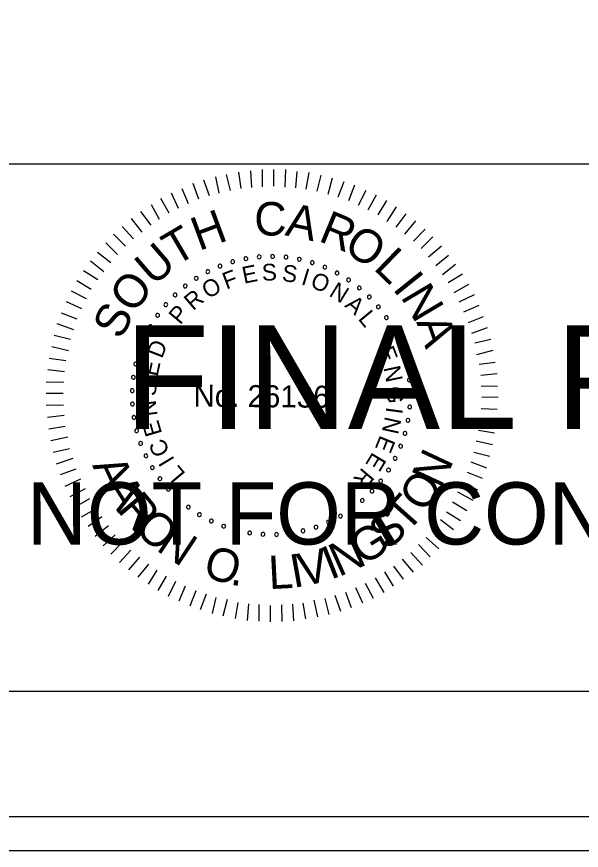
# Model space of a CAD drawing. Extents: x 967 to 1326, y 964 to 2584.
# Drawn here: x 1170.56 to 1189.3, y 1803.72 to 1831.36 of the extents above; entities that cross this region are included whole.
import ezdxf

# ---------------------------------------------------------------- set-up
doc = ezdxf.new("R2010")
doc.units = 0
for name, color, linetype in [('RD_SHT_Misc1', 7, 'Continuous'), ('RD_SHT_Misc2', 7, 'Continuous'), ('RD_XS_ExPaveRet', 7, 'Continuous'), ('RD_XS_TX_Elev_EX', 7, 'Continuous')]:
    doc.layers.add(name, color=color, linetype=linetype)

msp = doc.modelspace()

# ---------------------------------------------------------------- linework, layer by layer
at = {"layer": 'RD_SHT_Misc1'}
for p, q in [((1178.01, 1825.663), (1177.93, 1826.209)), ((1178.364, 1825.699), (1178.33, 1826.244)), ((1178.717, 1825.719), (1178.722, 1826.295)), ((1179.093, 1825.739), (1179.098, 1826.292)), ((1179.469, 1825.713), (1179.489, 1826.288)), ((1179.829, 1825.687), (1179.872, 1826.231)), ((1180.174, 1825.646), (1180.271, 1826.19)), ((1176.964, 1825.419), (1176.769, 1825.935)), ((1177.287, 1825.508), (1177.169, 1826.054)), ((1177.657, 1825.597), (1177.53, 1826.128)), ((1180.535, 1825.573), (1180.662, 1826.102)), ((1180.902, 1825.478), (1181.045, 1826.022)), ((1181.231, 1825.384), (1181.428, 1825.896)), ((1176.264, 1825.156), (1176.053, 1825.657)), ((1176.61, 1825.306), (1176.423, 1825.83)), ((1181.584, 1825.265), (1181.78, 1825.786)), ((1181.905, 1825.109), (1182.154, 1825.606)), ((1175.624, 1824.846), (1175.352, 1825.332)), ((1175.933, 1825.005), (1175.699, 1825.506)), ((1182.226, 1824.953), (1182.506, 1825.45)), ((1175.308, 1824.634), (1175.036, 1825.12)), ((1182.562, 1824.789), (1182.85, 1825.27)), ((1175.03, 1824.445), (1174.681, 1824.9)), ((1182.86, 1824.572), (1183.163, 1825.053)), ((1183.158, 1824.378), (1183.484, 1824.828)), ((1174.729, 1824.217), (1174.372, 1824.665)), ((1183.447, 1824.145), (1183.811, 1824.587)), ((1174.435, 1823.997), (1174.062, 1824.399)), ((1183.729, 1823.92), (1184.116, 1824.316)), ((1174.172, 1823.753), (1173.776, 1824.148)), ((1183.98, 1823.672), (1184.368, 1824.061)), ((1173.909, 1823.479), (1173.52, 1823.858)), ((1184.232, 1823.394), (1184.657, 1823.767)), ((1173.684, 1823.197), (1173.242, 1823.546)), ((1184.475, 1823.108), (1184.892, 1823.45)), ((1173.451, 1822.9), (1173.009, 1823.256)), ((1184.687, 1822.807), (1185.128, 1823.156)), ((1173.257, 1822.64), (1172.776, 1822.936)), ((1173.039, 1822.312), (1172.559, 1822.6)), ((1184.885, 1822.544), (1185.355, 1822.832)), ((1185.081, 1822.213), (1185.56, 1822.493)), ((1172.883, 1822.006), (1172.379, 1822.256)), ((1185.24, 1821.904), (1185.756, 1822.145)), ((1172.727, 1821.677), (1172.215, 1821.904)), ((1185.399, 1821.573), (1185.907, 1821.791)), ((1172.571, 1821.333), (1172.051, 1821.53)), ((1185.549, 1821.226), (1186.057, 1821.414)), ((1172.461, 1820.974), (1171.91, 1821.178)), ((1185.669, 1820.865), (1186.185, 1821.06)), ((1172.351, 1820.652), (1171.807, 1820.787)), ((1185.759, 1820.541), (1186.297, 1820.667)), ((1172.286, 1820.276), (1171.727, 1820.419)), ((1185.832, 1820.165), (1186.371, 1820.298)), ((1172.191, 1819.955), (1171.647, 1820.029)), ((1185.906, 1819.842), (1186.436, 1819.906)), ((1172.15, 1819.587), (1171.598, 1819.653)), ((1185.964, 1819.473), (1186.51, 1819.53)), ((1172.124, 1819.234), (1171.548, 1819.239)), ((1185.977, 1819.12), (1186.514, 1819.115)), ((1172.105, 1818.866), (1171.545, 1818.871)), ((1185.997, 1818.751), (1186.542, 1818.747)), ((1172.118, 1818.482), (1171.542, 1818.471)), ((1185.971, 1818.368), (1186.508, 1818.348)), ((1172.138, 1818.136), (1171.585, 1818.072)), ((1185.952, 1818.022), (1186.497, 1817.949)), ((1172.173, 1817.768), (1171.627, 1817.688)), ((1185.888, 1817.655), (1186.417, 1817.566)), ((1172.262, 1817.414), (1171.701, 1817.296)), ((1185.808, 1817.302), (1186.345, 1817.175)), ((1172.321, 1817.037), (1171.774, 1816.911)), ((1185.729, 1816.926), (1186.265, 1816.792)), ((1172.425, 1816.707), (1171.871, 1816.519)), ((1185.634, 1816.597), (1186.146, 1816.401)), ((1172.53, 1816.36), (1172.007, 1816.173)), ((1185.508, 1816.253), (1186.013, 1816.057)), ((1172.681, 1816.029), (1172.165, 1815.788)), ((1172.831, 1815.705), (1172.323, 1815.441)), ((1185.352, 1815.924), (1185.857, 1815.675)), ((1185.188, 1815.603), (1185.7, 1815.33)), ((1172.982, 1815.374), (1172.497, 1815.094)), ((1185.024, 1815.274), (1185.498, 1814.987)), ((1173.194, 1815.042), (1172.709, 1814.762)), ((1184.822, 1814.946), (1185.288, 1814.658)), ((1173.384, 1814.78), (1172.936, 1814.453)), ((1184.62, 1814.687), (1185.055, 1814.353)), ((1173.612, 1814.478), (1173.164, 1814.129)), ((1184.403, 1814.389), (1184.814, 1814.033)), ((1173.832, 1814.177), (1173.437, 1813.812)), ((1184.155, 1814.092), (1184.574, 1813.72)), ((1174.091, 1813.945), (1173.689, 1813.541)), ((1183.899, 1813.864), (1184.28, 1813.454)), ((1174.35, 1813.674), (1173.97, 1813.263)), ((1183.644, 1813.597), (1184.024, 1813.18)), ((1174.64, 1813.442), (1174.275, 1813.022)), ((1174.937, 1813.209), (1174.58, 1812.782)), ((1183.358, 1813.37), (1183.715, 1812.944)), ((1175.212, 1813.014), (1174.932, 1812.549)), ((1182.764, 1812.952), (1183.059, 1812.482)), ((1183.065, 1813.141), (1183.384, 1812.709)), ((1175.525, 1812.812), (1175.245, 1812.331)), ((1175.83, 1812.633), (1175.588, 1812.136)), ((1182.463, 1812.755), (1182.743, 1812.269)), ((1176.159, 1812.477), (1175.94, 1811.98)), ((1181.8, 1812.431), (1182.041, 1811.93)), ((1182.124, 1812.581), (1182.396, 1812.08)), ((1176.503, 1812.321), (1176.307, 1811.816)), ((1176.855, 1812.211), (1176.651, 1811.69)), ((1177.177, 1812.1), (1177.05, 1811.572)), ((1180.791, 1812.07), (1180.926, 1811.54)), ((1181.122, 1812.175), (1181.31, 1811.652)), ((1181.476, 1812.28), (1181.664, 1811.771)), ((1177.545, 1812.036), (1177.409, 1811.484)), ((1177.897, 1811.933), (1177.808, 1811.412)), ((1178.25, 1811.892), (1178.207, 1811.34)), ((1178.603, 1811.866), (1178.598, 1811.313)), ((1178.978, 1811.84), (1178.974, 1811.295)), ((1179.355, 1811.86), (1179.365, 1811.307)), ((1179.715, 1811.88), (1179.749, 1811.327)), ((1180.061, 1811.915), (1180.149, 1811.393)), ((1180.423, 1812.012), (1180.541, 1811.458))]:
    msp.add_line(p, q, dxfattribs=at)
for centre, start, end in [((1178.168, 1823.337), 10.6038, 190.6038), ((1178.609, 1823.397), 5.0653, 185.0653), ((1178.609, 1823.397), 185.0653, 5.0653), ((1179.055, 1823.414), 359.5268, 179.5268), ((1179.055, 1823.414), 179.5268, 359.5268), ((1179.5, 1823.388), 353.9884, 173.9884), ((1177.312, 1823.091), 21.6807, 201.6807), ((1177.734, 1823.235), 16.1422, 196.1422), ((1177.734, 1823.235), 196.1422, 16.1422), ((1178.168, 1823.337), 190.6038, 10.6038), ((1179.5, 1823.388), 173.9884, 353.9884), ((1179.94, 1823.319), 168.4499, 348.4499), ((1179.94, 1823.319), 348.4499, 168.4499), ((1180.372, 1823.208), 162.9114, 342.9114), ((1180.372, 1823.208), 342.9114, 162.9114), ((1180.79, 1823.056), 337.373, 157.373), ((1176.906, 1822.908), 27.2191, 207.2191), ((1176.906, 1822.908), 207.2191, 27.2191), ((1177.312, 1823.091), 201.6807, 21.6807), ((1180.79, 1823.056), 157.373, 337.373), ((1181.193, 1822.864), 151.8345, 331.8345), ((1181.193, 1822.864), 331.8345, 151.8345), ((1176.52, 1822.686), 32.7576, 212.7576), ((1176.52, 1822.686), 212.7576, 32.7576), ((1181.574, 1822.634), 146.2961, 326.2961), ((1181.574, 1822.634), 326.2961, 146.2961), ((1176.156, 1822.428), 38.2961, 218.2961), ((1176.156, 1822.428), 218.2961, 38.2961), ((1181.932, 1822.368), 140.7576, 320.7576), ((1181.932, 1822.368), 320.7576, 140.7576), ((1175.82, 1822.135), 43.8345, 223.8345), ((1175.82, 1822.135), 223.8345, 43.8345), ((1182.263, 1822.069), 135.2191, 315.2191), ((1182.263, 1822.069), 315.2191, 135.2191), ((1175.513, 1821.812), 49.373, 229.373), ((1175.513, 1821.812), 229.373, 49.373), ((1182.563, 1821.74), 129.6807, 309.6807), ((1182.563, 1821.74), 309.6807, 129.6807), ((1175.239, 1821.461), 54.9114, 234.9114), ((1175.239, 1821.461), 234.9114, 54.9114), ((1182.83, 1821.383), 124.1422, 304.1422), ((1182.83, 1821.383), 304.1422, 124.1422), ((1175, 1821.085), 60.4499, 240.4499), ((1175, 1821.085), 240.4499, 60.4499), ((1183.061, 1821.002), 118.6038, 298.6038), ((1183.061, 1821.002), 298.6038, 118.6038), ((1174.798, 1820.687), 65.9884, 245.9884), ((1174.798, 1820.687), 245.9884, 65.9884), ((1183.255, 1820.601), 113.0653, 293.0653), ((1183.255, 1820.601), 293.0653, 113.0653), ((1174.636, 1820.272), 71.5268, 251.5268), ((1174.636, 1820.272), 251.5268, 71.5268), ((1183.408, 1820.182), 107.5268, 287.5268), ((1183.408, 1820.182), 287.5268, 107.5268), ((1174.514, 1819.843), 77.0653, 257.0653), ((1174.514, 1819.843), 257.0653, 77.0653), ((1183.521, 1819.751), 101.9884, 281.9884), ((1183.521, 1819.751), 281.9884, 101.9884), ((1174.435, 1819.405), 82.6038, 262.6038), ((1174.435, 1819.405), 262.6038, 82.6038), ((1183.592, 1819.311), 96.4499, 276.4499), ((1183.592, 1819.311), 276.4499, 96.4499), ((1174.398, 1818.961), 88.1422, 268.1422), ((1174.398, 1818.961), 268.1422, 88.1422), ((1183.619, 1818.866), 90.9114, 270.9114), ((1183.619, 1818.866), 270.9114, 90.9114), ((1174.404, 1818.515), 93.6807, 273.6807), ((1174.404, 1818.515), 273.6807, 93.6807), ((1183.604, 1818.421), 85.373, 265.373), ((1183.604, 1818.421), 265.373, 85.373), ((1174.453, 1818.072), 99.2191, 279.2191), ((1174.453, 1818.072), 279.2191, 99.2191), ((1183.546, 1817.979), 79.8345, 259.8345), ((1183.546, 1817.979), 259.8345, 79.8345), ((1174.545, 1817.636), 104.7576, 284.7576), ((1174.545, 1817.636), 284.7576, 104.7576), ((1183.445, 1817.545), 74.2961, 254.2961), ((1183.445, 1817.545), 254.2961, 74.2961), ((1174.678, 1817.211), 110.2961, 290.2961), ((1174.678, 1817.211), 290.2961, 110.2961), ((1183.303, 1817.122), 68.7576, 248.7576), ((1183.303, 1817.122), 248.7576, 68.7576), ((1174.852, 1816.8), 115.8345, 295.8345), ((1174.852, 1816.8), 295.8345, 115.8345), ((1183.121, 1816.716), 63.2191, 243.2191), ((1183.121, 1816.716), 243.2191, 63.2191), ((1175.065, 1816.409), 121.373, 301.373), ((1175.065, 1816.409), 301.373, 121.373), ((1182.9, 1816.328), 57.6807, 237.6807), ((1182.9, 1816.328), 237.6807, 57.6807), ((1175.314, 1816.039), 126.9114, 306.9114), ((1175.314, 1816.039), 306.9114, 126.9114), ((1182.643, 1815.964), 52.1422, 232.1422), ((1182.643, 1815.964), 232.1422, 52.1422), ((1175.598, 1815.696), 132.4499, 312.4499), ((1175.598, 1815.696), 312.4499, 132.4499), ((1182.353, 1815.627), 46.6038, 226.6038), ((1182.353, 1815.627), 226.6038, 46.6038), ((1175.914, 1815.381), 137.9884, 317.9884), ((1175.914, 1815.381), 317.9884, 137.9884), ((1182.03, 1815.319), 41.0653, 221.0653), ((1176.258, 1815.099), 143.5268, 323.5268), ((1176.258, 1815.099), 323.5268, 143.5268), ((1181.68, 1815.043), 35.5268, 215.5268), ((1182.03, 1815.319), 221.0653, 41.0653), ((1176.629, 1814.851), 149.0653, 329.0653), ((1176.629, 1814.851), 329.0653, 149.0653), ((1181.305, 1814.803), 29.9884, 209.9884), ((1181.305, 1814.803), 209.9884, 29.9884), ((1181.68, 1815.043), 215.5268, 35.5268), ((1177.021, 1814.639), 154.6038, 334.6038), ((1177.021, 1814.639), 334.6038, 154.6038), ((1180.908, 1814.6), 24.4499, 204.4499), ((1180.908, 1814.6), 204.4499, 24.4499), ((1177.432, 1814.467), 160.1422, 340.1422), ((1177.432, 1814.467), 340.1422, 160.1422), ((1177.858, 1814.335), 165.6807, 345.6807), ((1177.858, 1814.335), 345.6807, 165.6807), ((1178.294, 1814.245), 351.2191, 171.2191), ((1179.627, 1814.232), 7.8345, 187.8345), ((1180.065, 1814.313), 13.373, 193.373), ((1180.065, 1814.313), 193.373, 13.373), ((1180.494, 1814.436), 18.9114, 198.9114), ((1180.494, 1814.436), 198.9114, 18.9114), ((1178.294, 1814.245), 171.2191, 351.2191), ((1178.737, 1814.198), 356.7576, 176.7576), ((1178.737, 1814.198), 176.7576, 356.7576), ((1179.183, 1814.193), 2.2961, 182.2961), ((1179.183, 1814.193), 182.2961, 2.2961), ((1179.627, 1814.232), 187.8345, 7.8345)]:
    msp.add_arc(centre, 0.0627, start, end, dxfattribs=at)
at = {"layer": 'RD_XS_ExPaveRet'}
for points in [[(967.409, 1803.72), (1326.285, 1803.72), (1326.285, 2023.72), (967.409, 2023.72)], [(988.525, 1804.84), (1326.285, 1804.84), (1326.285, 2022.6), (988.525, 2022.6)]]:
    msp.add_lwpolyline(points, close=True, dxfattribs=at)
at = {"layer": 'RD_XS_TX_Elev_EX'}
for p, q in [((996.114, 1826.486), (1323.886, 1826.486)), ((1323.886, 1808.983), (996.114, 1808.983))]:
    msp.add_line(p, q, dxfattribs=at)

# ---------------------------------------------------------------- texts
at = {"layer": 'RD_SHT_Misc1'}
for s, height, rotation, p in [('C', 1.11, 359.5482, (1178.442, 1824.108)), ('A', 1.11, 348.1981, (1179.439, 1824.115)), ('H', 1.11, 20.3637, (1176.614, 1823.587)), ('R', 1.11, 337.4344, (1180.541, 1823.937)), ('T', 1.11, 30.4992, (1175.828, 1823.072)), ('O', 1.108, 326.5869, (1181.366, 1823.609)), ('U', 1.11, 40.8022, (1175.102, 1822.403)), ('L', 1.11, 315.9488, (1182.373, 1823.003)), ('E', 0.557, 11.4103, (1178.103, 1822.503)), ('S', 0.557, 2.208, (1178.709, 1822.601)), ('S', 0.557, 352.6608, (1179.346, 1822.599)), ('O', 1.11, 52.0267, (1174.435, 1821.474)), ('F', 0.557, 20.6127, (1177.52, 1822.309)), ('I', 0.557, 343.1136, (1179.975, 1822.491)), ('O', 0.557, 338.4392, (1180.274, 1822.401)), ('I', 1.11, 308.6613, (1183.011, 1822.338)), ('O', 0.557, 30.8477, (1176.917, 1821.987)), ('N', 0.557, 328.2042, (1180.896, 1822.12)), ('N', 1.11, 300.7037, (1183.285, 1822.075)), ('R', 0.557, 40.3949, (1176.415, 1821.594)), ('A', 0.557, 318.657, (1181.424, 1821.762)), ('S', 1.108, 63.2511, (1174.029, 1820.619)), ('P', 0.557, 49.9421, (1175.985, 1821.124)), ('L', 0.557, 309.4546, (1181.869, 1821.339)), ('A', 1.11, 289.4792, (1183.814, 1821.243)), ('D', 0.557, 69.0364, (1175.386, 1820.003)), ('E', 0.557, 291.049, (1182.53, 1820.307)), ('E', 0.557, 78.2388, (1175.238, 1819.407)), ('N', 0.557, 281.8466, (1182.728, 1819.726)), ('S', 0.557, 87.786, (1175.187, 1818.772)), ('No. 26136', 0.7311, 359.5268, (1176.429, 1818.43)), ('G', 0.557, 272.2995, (1182.833, 1819.097)), ('N', 0.557, 97.3332, (1175.242, 1818.137)), ('I', 0.557, 262.4084, (1182.83, 1818.437)), ('E', 0.557, 106.5355, (1175.394, 1817.541)), ('N', 0.557, 257.7339, (1182.789, 1818.127)), ('C', 0.557, 116.4266, (1175.661, 1816.938)), ('E', 0.557, 248.1867, (1182.628, 1817.511)), ('I', 0.557, 121.1011, (1175.823, 1816.67)), ('E', 0.557, 238.9844, (1182.378, 1816.949)), ('N', 1.105, 64.8922, (1184.632, 1815.684)), ('A', 1.105, 294.7297, (1173.062, 1816.486)), ('L', 0.557, 129.9595, (1176.187, 1816.204)), ('R', 0.557, 229.782, (1182.041, 1816.435)), ('O', 1.105, 56.2059, (1184.102, 1814.874)), ('A', 1.105, 302.2892, (1173.414, 1815.72)), ('R', 1.105, 309.8487, (1173.865, 1815.007)), ('T', 1.105, 48.2685, (1183.515, 1814.211)), ('O', 1.105, 317.7861, (1174.434, 1814.33)), ('S', 1.105, 40.3311, (1182.842, 1813.636)), ('N', 1.105, 326.4725, (1175.158, 1813.686)), ('G', 1.105, 32.0198, (1182.059, 1813.14)), ('N', 1.105, 24.0824, (1181.252, 1812.776)), ('O', 1.105, 342.3472, (1176.697, 1812.82)), ('V', 1.105, 12.7741, (1180.033, 1812.457)), ('I', 1.105, 21.4605, (1180.976, 1812.681)), ('L', 1.105, 2.9677, (1178.943, 1812.379)), ('I', 1.105, 10.1523, (1179.743, 1812.418)), ('.', 1.105, 351.0336, (1177.623, 1812.536))]:
    msp.add_text(s, height=height, rotation=rotation, dxfattribs=at).set_placement(p)
at = {"layer": 'RD_SHT_Misc2'}
for s, height, p in [('FINAL PLANS', 3.4375, (1174.145, 1817.685)), ('NOT FOR CONSTRUCTION', 2.0625, (1170.901, 1813.86))]:
    msp.add_text(s, height=height, dxfattribs=at).set_placement(p)

doc.saveas('drawing.dxf')
